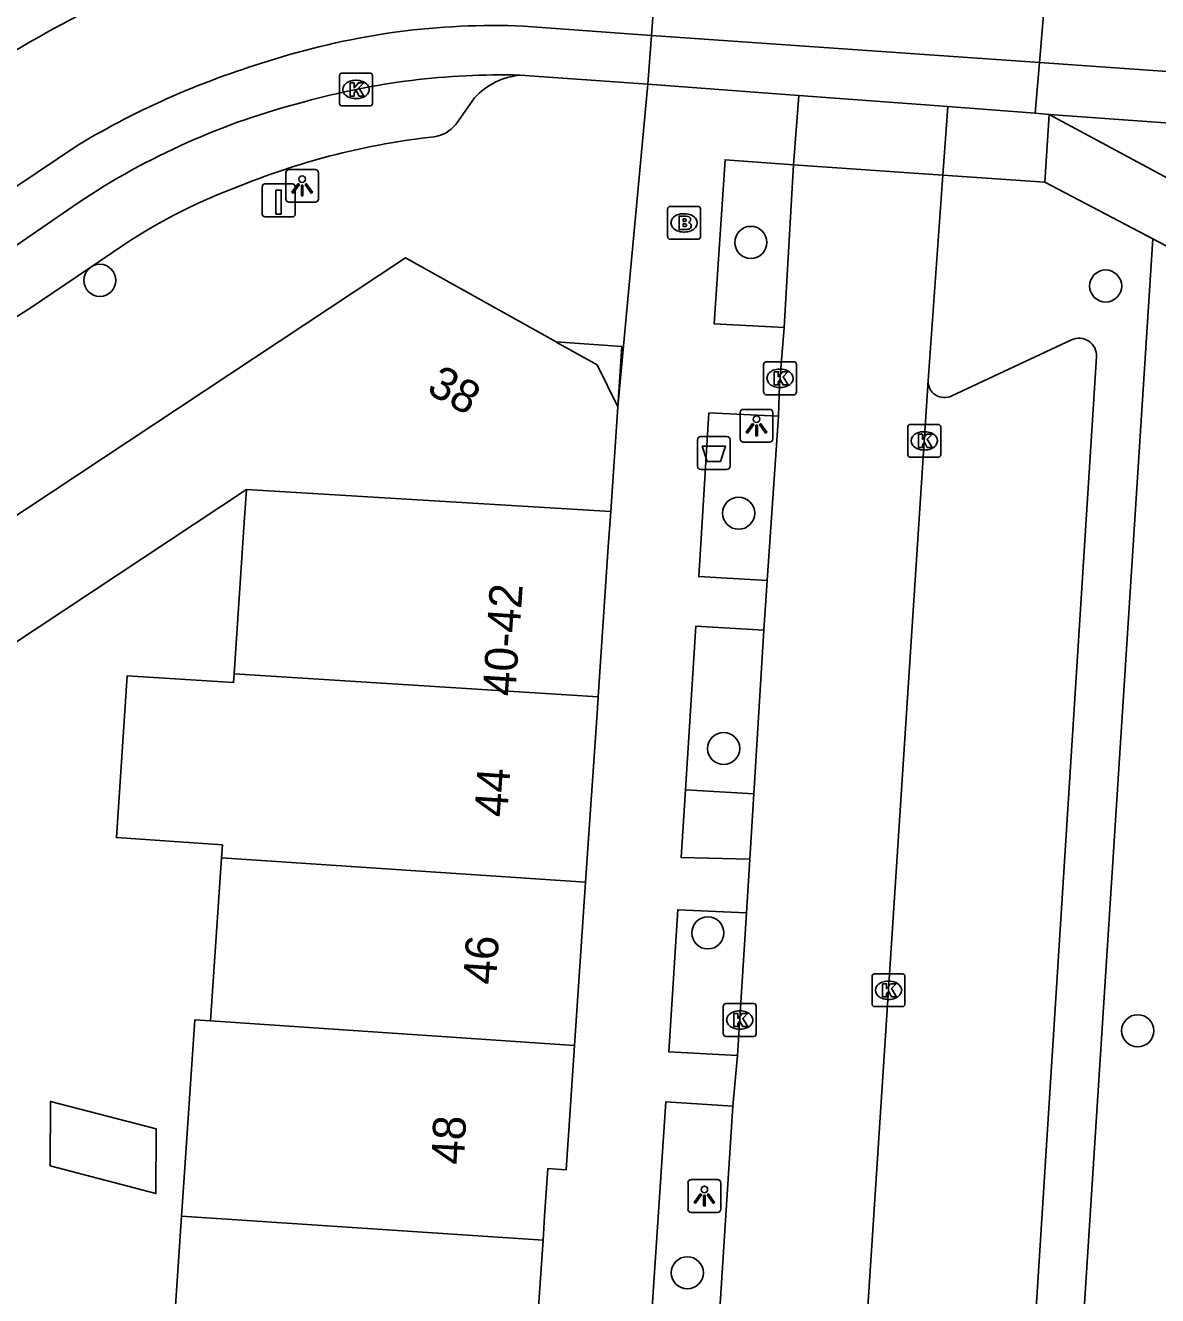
# Model space of a CAD drawing. Extents: x 159961 to 160856, y 382704 to 383353.
# Drawn here: x 160554.44 to 160588.94, y 382899.59 to 382938.31 of the extents above; entities that cross this region are included whole.
import ezdxf

# ---------------------------------------------------------------- set-up
doc = ezdxf.new("R2010")
doc.units = 0
for name, color, linetype in [('IMGEO_Afvalbak', 7, 'Continuous'), ('IMGEO_Boom', 7, 'Continuous'), ('IMGEO_Brandkraan', 7, 'Continuous'), ('IMGEO_Groenvoorziening', 7, 'Continuous'), ('IMGEO_Kolk', 7, 'Continuous'), ('IMGEO_Laadpaal', 7, 'Continuous'), ('IMGEO_Lichtpunt', 7, 'Continuous'), ('IMGEO_Pand', 7, 'Continuous'), ('IMGEO_Pand_nummerreeks', 7, 'Continuous'), ('IMGEO_Pand_overbouw', 7, 'Continuous'), ('IMGEO_Parkeervlak_open', 7, 'Continuous'), ('IMGEO_Rijbaan_lokaal_gesloten', 7, 'Continuous'), ('IMGEO_Rijbaan_lokaal_open', 7, 'Continuous'), ('IMGEO_Voetpad_halfverhard', 7, 'Continuous'), ('IMGEO_Voetpad_open', 7, 'Continuous')]:
    doc.layers.add(name, color=color, linetype=linetype)

msp = doc.modelspace()

# ---------------------------------------------------------------- linework, layer by layer
at = {"layer": 'IMGEO_Afvalbak'}
for p, q in [((160575.023, 382925.776), (160575.813, 382925.776)), ((160575.813, 382925.776), (160575.023, 382925.776)), ((160574.923, 382924.876), (160574.923, 382925.676)), ((160574.923, 382925.676), (160574.923, 382924.876)), ((160575.913, 382925.676), (160575.913, 382924.876)), ((160575.913, 382924.876), (160575.913, 382925.676)), ((160575.813, 382924.776), (160575.023, 382924.776)), ((160575.023, 382924.776), (160575.813, 382924.776))]:
    msp.add_line(p, q, dxfattribs=at)
msp.add_lwpolyline([(160575.066, 382925.49), (160575.77, 382925.49), (160575.621, 382925.02), (160575.215, 382925.02), (160575.066, 382925.49)], dxfattribs=at)
for centre, start, end in [((160575.023, 382925.676), 90, 180), ((160575.023, 382925.676), 90, 180), ((160575.813, 382925.676), 0, 90), ((160575.813, 382925.676), 360, 90), ((160575.023, 382924.876), 180, 270), ((160575.023, 382924.876), 180, 270), ((160575.813, 382924.876), 270, 0), ((160575.813, 382924.876), 270, 0)]:
    msp.add_arc(centre, 0.1, start, end, dxfattribs=at)
at = {"layer": 'IMGEO_Boom'}
for centre in [(160576.546, 382931.699), (160556.709, 382930.541), (160587.357, 382930.369), (160576.174, 382923.442), (160575.717, 382916.268), (160575.234, 382910.647), (160588.334, 382907.665), (160574.61, 382900.287)]:
    msp.add_circle(centre, 0.489, dxfattribs=at)
at = {"layer": 'IMGEO_Brandkraan'}
for p, q in [((160574.011, 382931.868), (160574.011, 382932.72)), ((160574.086, 382932.794), (160574.938, 382932.794)), ((160575.012, 382932.72), (160575.012, 382931.868)), ((160574.499, 382932.574), (160574.524, 382932.574)), ((160574.522, 382932.014), (160574.497, 382932.014)), ((160574.938, 382931.794), (160574.086, 382931.794))]:
    msp.add_line(p, q, dxfattribs=at)
for points in [[(160574.011, 382931.868), (160574.011, 382932.72)], [(160574.086, 382932.794), (160574.938, 382932.794)], [(160575.012, 382932.72), (160575.012, 382931.868)], [(160574.359, 382932.494), (160574.359, 382932.094), (160574.572, 382932.094)], [(160574.59, 382932.494), (160574.359, 382932.494)], [(160574.538, 382932.413), (160574.484, 382932.413), (160574.484, 382932.337)], [(160574.484, 382932.337), (160574.537, 382932.337)], [(160574.546, 382932.261), (160574.484, 382932.261), (160574.484, 382932.18)], [(160574.484, 382932.18), (160574.546, 382932.18)], [(160574.938, 382931.794), (160574.086, 382931.794)]]:
    msp.add_lwpolyline(points, dxfattribs=at)
for centre, radius, start, end in [((160574.088, 382932.718), 0.0765, 91.552, 178.448), ((160574.088, 382932.718), 0.0765, 91.552, 178.448), ((160574.936, 382932.718), 0.0765, 1.552, 88.448), ((160574.936, 382932.718), 0.0765, 1.552, 88.448), ((160574.539, 382932.375), 0.0379, 267.8285, 90.9355), ((160574.594, 382932.349), 0.145, 59.4692, 91.5367), ((160574.619, 382932.396), 0.0922, 285.5137, 58.1501), ((160574.624, 382932.204), 0.105, 301.3115, 78.989), ((160574.547, 382932.22), 0.0404, 269.8759, 90.5077), ((160574.578, 382932.345), 0.251, 268.6676, 293.5347), ((160574.088, 382931.87), 0.0765, 181.552, 268.448), ((160574.088, 382931.87), 0.0765, 181.552, 268.448), ((160574.936, 382931.87), 0.0765, 271.552, 358.448), ((160574.936, 382931.87), 0.0765, 271.552, 358.448)]:
    msp.add_arc(centre, radius, start, end, dxfattribs=at)
for centre, major_axis, ratio, start_param, end_param in [((160574.498, 382932.294), (-0.387, 0.002), 0.722429, 4.712389, 7.853982), ((160574.523, 382932.294), (-0.39, 0.002), 0.717154, 1.570796, 4.712389)]:
    msp.add_ellipse(centre, major_axis=major_axis, ratio=ratio, start_param=start_param, end_param=end_param, dxfattribs=at)
at = {"layer": 'IMGEO_Groenvoorziening'}
for points in [[(160585.634, 382882.567), (160588.794, 382931.802)], [(160576.637, 382914.885), (160574.552, 382915.005)]]:
    msp.add_lwpolyline(points, dxfattribs=at)
at = {"layer": 'IMGEO_Kolk'}
for p, q in [((160564.013, 382935.934), (160564.013, 382936.786)), ((160564.088, 382936.86), (160564.94, 382936.86)), ((160564.501, 382936.64), (160564.526, 382936.64)), ((160565.014, 382936.786), (160565.014, 382935.934)), ((160564.94, 382935.86), (160564.088, 382935.86)), ((160564.524, 382936.08), (160564.499, 382936.08)), ((160577.011, 382928.055), (160577.863, 382928.055)), ((160576.936, 382927.129), (160576.936, 382927.981)), ((160577.424, 382927.835), (160577.449, 382927.835)), ((160577.937, 382927.981), (160577.937, 382927.129)), ((160577.447, 382927.275), (160577.422, 382927.275)), ((160577.863, 382927.055), (160577.011, 382927.055)), ((160581.404, 382926.148), (160582.256, 382926.148)), ((160581.329, 382925.222), (160581.329, 382926.074)), ((160581.817, 382925.928), (160581.842, 382925.928)), ((160582.33, 382926.074), (160582.33, 382925.222)), ((160581.84, 382925.368), (160581.815, 382925.368)), ((160582.256, 382925.148), (160581.404, 382925.148)), ((160580.24, 382908.474), (160580.24, 382909.326)), ((160580.315, 382909.4), (160581.167, 382909.4)), ((160580.728, 382909.18), (160580.753, 382909.18)), ((160581.241, 382909.326), (160581.241, 382908.474)), ((160575.707, 382907.566), (160575.707, 382908.418)), ((160575.782, 382908.492), (160576.634, 382908.492)), ((160576.708, 382908.418), (160576.708, 382907.566)), ((160581.167, 382908.4), (160580.315, 382908.4)), ((160580.751, 382908.62), (160580.726, 382908.62)), ((160576.195, 382908.272), (160576.22, 382908.272)), ((160576.218, 382907.712), (160576.193, 382907.712)), ((160576.634, 382907.492), (160575.782, 382907.492))]:
    msp.add_line(p, q, dxfattribs=at)
for points in [[(160564.013, 382935.934), (160564.013, 382936.786)], [(160564.088, 382936.86), (160564.94, 382936.86)], [(160565.014, 382936.786), (160565.014, 382935.934)], [(160564.334, 382936.56), (160564.457, 382936.56), (160564.457, 382936.409), (160564.587, 382936.56), (160564.751, 382936.56), (160564.605, 382936.409), (160564.758, 382936.16), (160564.606, 382936.16), (160564.521, 382936.324), (160564.457, 382936.257), (160564.457, 382936.16), (160564.334, 382936.16), (160564.334, 382936.56)], [(160564.94, 382935.86), (160564.088, 382935.86)], [(160577.011, 382928.055), (160577.863, 382928.055)], [(160576.936, 382927.129), (160576.936, 382927.981)], [(160577.257, 382927.755), (160577.38, 382927.755), (160577.38, 382927.604), (160577.51, 382927.755), (160577.674, 382927.755), (160577.528, 382927.604), (160577.681, 382927.355), (160577.529, 382927.355), (160577.444, 382927.519), (160577.38, 382927.452), (160577.38, 382927.355), (160577.257, 382927.355), (160577.257, 382927.755)], [(160577.937, 382927.981), (160577.937, 382927.129)], [(160577.863, 382927.055), (160577.011, 382927.055)], [(160581.404, 382926.148), (160582.256, 382926.148)], [(160581.329, 382925.222), (160581.329, 382926.074)], [(160581.65, 382925.848), (160581.773, 382925.848), (160581.773, 382925.697), (160581.903, 382925.848), (160582.067, 382925.848), (160581.921, 382925.697), (160582.074, 382925.448), (160581.922, 382925.448), (160581.837, 382925.612), (160581.773, 382925.545), (160581.773, 382925.448), (160581.65, 382925.448), (160581.65, 382925.848)], [(160582.33, 382926.074), (160582.33, 382925.222)], [(160582.256, 382925.148), (160581.404, 382925.148)], [(160580.24, 382908.474), (160580.24, 382909.326)], [(160580.315, 382909.4), (160581.167, 382909.4)], [(160580.561, 382909.1), (160580.684, 382909.1), (160580.684, 382908.949), (160580.814, 382909.1), (160580.978, 382909.1), (160580.832, 382908.949), (160580.985, 382908.7), (160580.833, 382908.7), (160580.748, 382908.864), (160580.684, 382908.797), (160580.684, 382908.7), (160580.561, 382908.7), (160580.561, 382909.1)], [(160581.241, 382909.326), (160581.241, 382908.474)], [(160575.707, 382907.566), (160575.707, 382908.418)], [(160575.782, 382908.492), (160576.634, 382908.492)], [(160576.708, 382908.418), (160576.708, 382907.566)], [(160581.167, 382908.4), (160580.315, 382908.4)], [(160576.028, 382908.192), (160576.151, 382908.192), (160576.151, 382908.041), (160576.281, 382908.192), (160576.445, 382908.192), (160576.299, 382908.041), (160576.452, 382907.792), (160576.3, 382907.792), (160576.215, 382907.956), (160576.151, 382907.889), (160576.151, 382907.792), (160576.028, 382907.792), (160576.028, 382908.192)], [(160576.634, 382907.492), (160575.782, 382907.492)]]:
    msp.add_lwpolyline(points, dxfattribs=at)
for centre, start, end in [((160564.09, 382936.784), 91.552, 178.448), ((160564.09, 382936.784), 91.552, 178.448), ((160564.938, 382936.784), 1.552, 88.448), ((160564.938, 382936.784), 1.552, 88.448), ((160564.09, 382935.936), 181.552, 268.448), ((160564.09, 382935.936), 181.552, 268.448), ((160564.938, 382935.936), 271.552, 358.448), ((160564.938, 382935.936), 271.552, 358.448), ((160577.013, 382927.979), 91.552, 178.448), ((160577.013, 382927.979), 91.552, 178.448), ((160577.861, 382927.979), 1.552, 88.448), ((160577.861, 382927.979), 1.552, 88.448), ((160577.013, 382927.131), 181.552, 268.448), ((160577.013, 382927.131), 181.552, 268.448), ((160577.861, 382927.131), 271.552, 358.448), ((160577.861, 382927.131), 271.552, 358.448), ((160581.406, 382926.072), 91.552, 178.448), ((160581.406, 382926.072), 91.552, 178.448), ((160582.254, 382926.072), 1.552, 88.448), ((160582.254, 382926.072), 1.552, 88.448), ((160581.406, 382925.224), 181.552, 268.448), ((160581.406, 382925.224), 181.552, 268.448), ((160582.254, 382925.224), 271.552, 358.448), ((160582.254, 382925.224), 271.552, 358.448), ((160580.317, 382909.324), 91.552, 178.448), ((160580.317, 382909.324), 91.552, 178.448), ((160581.165, 382909.324), 1.552, 88.448), ((160581.165, 382909.324), 1.552, 88.448), ((160575.784, 382908.416), 91.552, 178.448), ((160575.784, 382908.416), 91.552, 178.448), ((160576.632, 382908.416), 1.552, 88.448), ((160576.632, 382908.416), 1.552, 88.448), ((160580.317, 382908.476), 181.552, 268.448), ((160580.317, 382908.476), 181.552, 268.448), ((160581.165, 382908.476), 271.552, 358.448), ((160581.165, 382908.476), 271.552, 358.448), ((160575.784, 382907.568), 181.552, 268.448), ((160575.784, 382907.568), 181.552, 268.448), ((160576.632, 382907.568), 271.552, 358.448), ((160576.632, 382907.568), 271.552, 358.448)]:
    msp.add_arc(centre, 0.0765, start, end, dxfattribs=at)
for centre, major_axis, ratio, start_param, end_param in [((160564.5, 382936.36), (-0.387, 0.002), 0.722429, 4.712389, 7.853982), ((160564.525, 382936.36), (-0.39, 0.002), 0.717154, 1.570796, 4.712389), ((160577.423, 382927.555), (-0.387, 0.002), 0.722429, 4.712389, 7.853982), ((160577.448, 382927.555), (-0.39, 0.002), 0.717154, 1.570796, 4.712389), ((160581.816, 382925.648), (-0.387, 0.002), 0.722429, 4.712389, 7.853982), ((160581.841, 382925.648), (-0.39, 0.002), 0.717154, 1.570796, 4.712389), ((160580.727, 382908.9), (-0.387, 0.002), 0.722429, 4.712389, 7.853982), ((160580.752, 382908.9), (-0.39, 0.002), 0.717154, 1.570796, 4.712389), ((160576.194, 382907.992), (-0.387, 0.002), 0.722429, 4.712389, 7.853982), ((160576.219, 382907.992), (-0.39, 0.002), 0.717154, 1.570796, 4.712389)]:
    msp.add_ellipse(centre, major_axis=major_axis, ratio=ratio, start_param=start_param, end_param=end_param, dxfattribs=at)
at = {"layer": 'IMGEO_Laadpaal'}
for p, q in [((160562.576, 382933.48), (160561.735, 382933.48)), ((160562.576, 382933.48), (160561.735, 382933.48)), ((160561.66, 382933.396), (160561.66, 382932.555)), ((160561.66, 382933.396), (160561.66, 382932.555)), ((160562.66, 382932.564), (160562.66, 382933.405)), ((160562.66, 382932.564), (160562.66, 382933.405)), ((160561.744, 382932.48), (160562.585, 382932.48)), ((160561.744, 382932.48), (160562.585, 382932.48))]:
    msp.add_line(p, q, dxfattribs=at)
msp.add_lwpolyline([(160562.075, 382933.293), (160562.235, 382933.293), (160562.235, 382932.56), (160562.075, 382932.56), (160562.075, 382933.293)], dxfattribs=at)
for centre, start, end in [((160561.738, 382933.402), 92.4484, 184.2845), ((160561.738, 382933.402), 92.4484, 184.2845), ((160562.582, 382933.402), 2.4484, 94.2845), ((160562.582, 382933.402), 2.4484, 94.2845), ((160561.738, 382932.558), 182.4484, 274.2845), ((160561.738, 382932.558), 182.4484, 274.2845), ((160562.582, 382932.558), 272.4484, 4.2845), ((160562.582, 382932.558), 272.4484, 4.2845)]:
    msp.add_arc(centre, 0.0779, start, end, dxfattribs=at)
at = {"layer": 'IMGEO_Lichtpunt'}
for p, q in [((160563.278, 382933.922), (160562.47, 382933.922)), ((160563.278, 382933.922), (160562.47, 382933.922)), ((160562.376, 382933.827), (160562.376, 382933.02)), ((160562.376, 382933.827), (160562.376, 382933.02)), ((160563.372, 382933.02), (160563.372, 382933.827)), ((160563.372, 382933.02), (160563.372, 382933.827)), ((160562.47, 382932.926), (160563.278, 382932.926)), ((160562.47, 382932.926), (160563.278, 382932.926)), ((160576.221, 382926.512), (160576.221, 382925.705)), ((160576.221, 382926.512), (160576.221, 382925.705)), ((160577.123, 382926.607), (160576.315, 382926.607)), ((160577.123, 382926.607), (160576.315, 382926.607)), ((160577.217, 382925.705), (160577.217, 382926.512)), ((160577.217, 382925.705), (160577.217, 382926.512)), ((160576.315, 382925.611), (160577.123, 382925.611)), ((160576.315, 382925.611), (160577.123, 382925.611)), ((160574.631, 382903.03), (160574.631, 382902.223)), ((160574.631, 382903.03), (160574.631, 382902.223)), ((160575.533, 382903.125), (160574.725, 382903.125)), ((160575.533, 382903.125), (160574.725, 382903.125)), ((160575.627, 382902.223), (160575.627, 382903.03)), ((160575.627, 382902.223), (160575.627, 382903.03)), ((160574.725, 382902.129), (160575.533, 382902.129)), ((160574.725, 382902.129), (160575.533, 382902.129))]:
    msp.add_line(p, q, dxfattribs=at)
for points in [[(160562.75, 382933.491), (160562.789, 382933.463), (160562.601, 382933.201), (160562.563, 382933.228), (160562.75, 382933.491)], [(160562.962, 382933.463), (160563, 382933.49), (160563.187, 382933.228), (160563.148, 382933.2), (160562.962, 382933.463)], [(160562.852, 382933.443), (160562.899, 382933.443), (160562.899, 382933.121), (160562.852, 382933.121), (160562.852, 382933.443)], [(160576.595, 382926.176), (160576.634, 382926.148), (160576.446, 382925.886), (160576.408, 382925.913), (160576.595, 382926.176)], [(160576.697, 382926.128), (160576.744, 382926.128), (160576.744, 382925.806), (160576.697, 382925.806), (160576.697, 382926.128)], [(160576.807, 382926.148), (160576.845, 382926.175), (160577.032, 382925.913), (160576.993, 382925.885), (160576.807, 382926.148)], [(160575.005, 382902.694), (160575.044, 382902.666), (160574.856, 382902.404), (160574.818, 382902.431), (160575.005, 382902.694)], [(160575.107, 382902.646), (160575.154, 382902.646), (160575.154, 382902.324), (160575.107, 382902.324), (160575.107, 382902.646)], [(160575.217, 382902.666), (160575.255, 382902.693), (160575.442, 382902.431), (160575.403, 382902.403), (160575.217, 382902.666)]]:
    msp.add_lwpolyline(points, dxfattribs=at)
for centre in [(160562.875, 382933.625), (160576.72, 382926.31), (160575.13, 382902.828)]:
    msp.add_circle(centre, 0.0994, dxfattribs=at)
for centre, start, end in [((160562.47, 382933.827), 90, 180), ((160562.47, 382933.827), 90, 180), ((160563.278, 382933.827), 0, 90), ((160563.278, 382933.827), 0, 90), ((160562.47, 382933.02), 180, 270), ((160562.47, 382933.02), 180, 270), ((160563.278, 382933.02), 270, 0), ((160563.278, 382933.02), 270, 360), ((160576.315, 382926.512), 90, 180), ((160576.315, 382926.512), 90, 180), ((160577.123, 382926.512), 0, 90), ((160577.123, 382926.512), 0, 90), ((160576.315, 382925.705), 180, 270), ((160576.315, 382925.705), 180, 270), ((160577.123, 382925.705), 270, 0), ((160577.123, 382925.705), 270, 360), ((160574.725, 382903.03), 90, 180), ((160574.725, 382903.03), 90, 180), ((160575.533, 382903.03), 0, 90), ((160575.533, 382903.03), 0, 90), ((160574.725, 382902.223), 180, 270), ((160574.725, 382902.223), 180, 270), ((160575.533, 382902.223), 270, 0), ((160575.533, 382902.223), 270, 360)]:
    msp.add_arc(centre, 0.0946, start, end, dxfattribs=at)
at = {"layer": 'IMGEO_Pand'}
for points in [[(160548.356, 382919.53), (160566.024, 382931.226), (160570.61, 382928.664), (160570.636, 382928.65), (160571.865, 382927.963), (160572.49, 382926.689)], [(160572.49, 382926.689), (160572.275, 382923.497)], [(160548.356, 382919.53), (160550.128, 382916.853), (160561.177, 382924.168)], [(160560.797, 382918.55), (160561.109, 382923.159), (160561.177, 382924.168)], [(160561.177, 382924.168), (160572.275, 382923.497)], [(160572.275, 382923.497), (160572.202, 382922.421), (160571.893, 382917.847)], [(160560.797, 382918.55), (160560.779, 382918.281), (160557.545, 382918.486), (160557.212, 382913.553), (160560.445, 382913.334), (160560.418, 382912.933)], [(160571.893, 382917.847), (160560.797, 382918.55)], [(160571.893, 382917.847), (160571.859, 382917.347), (160571.511, 382912.196)], [(160560.082, 382907.962), (160560.418, 382912.933)], [(160560.418, 382912.933), (160571.511, 382912.196)], [(160571.511, 382912.196), (160571.174, 382907.212)], [(160560.082, 382907.962), (160559.604, 382907.994), (160559.249, 382902.745), (160559.2, 382902.014)], [(160571.174, 382907.212), (160560.082, 382907.962)], [(160571.174, 382907.212), (160570.918, 382903.429), (160570.361, 382903.466), (160570.263, 382902.012), (160570.214, 382901.282)], [(160555.191, 382903.543), (160555.201, 382905.51), (160558.429, 382904.671), (160558.419, 382902.703), (160555.191, 382903.543)], [(160558.833, 382896.589), (160558.964, 382898.52), (160559.2, 382902.014)], [(160559.2, 382902.014), (160570.214, 382901.282)], [(160570.214, 382901.282), (160569.977, 382897.787), (160569.847, 382895.857)]]:
    msp.add_lwpolyline(points, dxfattribs=at)
at = {"layer": 'IMGEO_Pand_overbouw'}
msp.add_lwpolyline([(160572.614, 382928.529), (160570.61, 382928.664), (160570.636, 382928.65), (160571.865, 382927.963), (160572.49, 382926.689)], close=True, dxfattribs=at)
at = {"layer": 'IMGEO_Parkeervlak_open'}
for points in [[(160586.314, 382928.724), (160582.667, 382927.021)], [(160584.487, 382887.345), (160587.079, 382928.212)]]:
    msp.add_lwpolyline(points, dxfattribs=at)
for centre, radius, start, end in [((160586.545, 382928.241), 0.535, 356.8879, 115.5248), ((160582.443, 382927.463), 0.496, 177.3666, 296.8494)]:
    msp.add_arc(centre, radius, start, end, dxfattribs=at)
at = {"layer": 'IMGEO_Rijbaan_lokaal_gesloten'}
for points in [[(160573.519, 382938.007), (160569.62, 382938.295)], [(160585.337, 382937.184), (160616.323, 382934.993), (160616.183, 382933.536)], [(160573.407, 382936.518), (160569.518, 382936.799)], [(160585.637, 382935.602), (160585.207, 382935.643)], [(160585.637, 382935.602), (160591.872, 382935.149), (160602.388, 382934.447), (160606.128, 382934.233), (160616.183, 382933.536)], [(160556.038, 382934.664), (160528.518, 382916.17)], [(160556.052, 382932.908), (160553.525, 382931.179), (160532.63, 382917.129)]]:
    msp.add_lwpolyline(points, dxfattribs=at)
for centre, radius, start, end in [((160568.72, 382913.478), 28.141, 105.7061, 124.2743), ((160568.747, 382915.902), 22.41, 87.7675, 107.4386), ((160569.305, 382912.462), 25.864, 106.3346, 120.861), ((160568.971, 382914.276), 22.53, 88.608, 105.5024), ((160568.495, 382914.293), 22.391, 104.3406, 123.76)]:
    msp.add_arc(centre, radius, start, end, dxfattribs=at)
at = {"layer": 'IMGEO_Rijbaan_lokaal_open'}
for points in [[(160573.775, 382941.428), (160573.519, 382938.007)], [(160585.624, 382940.588), (160585.337, 382937.184)], [(160573.519, 382938.007), (160573.407, 382936.518)], [(160585.337, 382937.184), (160573.519, 382938.007)], [(160585.207, 382935.643), (160585.337, 382937.184)], [(160578.01, 382936.176), (160573.407, 382936.518)], [(160577.849, 382934.058), (160578.01, 382936.176)], [(160578.01, 382936.176), (160582.548, 382935.84)], [(160582.398, 382933.745), (160582.548, 382935.84)], [(160582.548, 382935.84), (160585.207, 382935.643)], [(160577.849, 382934.058), (160577.566, 382929.1)], [(160582.398, 382933.745), (160577.849, 382934.058)], [(160581.948, 382927.486), (160582.398, 382933.745)], [(160577.566, 382929.1), (160577.42, 382927.341), (160577.386, 382926.4)], [(160579.079, 382883.337), (160581.948, 382927.486)], [(160577.386, 382926.4), (160577.048, 382921.391)], [(160577.048, 382921.391), (160576.946, 382919.875)], [(160576.946, 382919.875), (160576.637, 382914.885)], [(160576.637, 382914.885), (160576.513, 382912.893)], [(160576.513, 382912.893), (160576.412, 382911.263)], [(160576.412, 382911.263), (160576.142, 382906.91)], [(160576.142, 382906.91), (160575.998, 382905.366)], [(160575.998, 382905.366), (160575.423, 382896.333)]]:
    msp.add_lwpolyline(points, dxfattribs=at)
at = {"layer": 'IMGEO_Voetpad_halfverhard'}
for points in [[(160616.315, 382929.418), (160594.851, 382931.047), (160593.305, 382931.469), (160585.637, 382935.602)], [(160585.502, 382933.53), (160588.794, 382931.802)], [(160588.794, 382931.802), (160591.356, 382930.458)]]:
    msp.add_lwpolyline(points, dxfattribs=at)
at = {"layer": 'IMGEO_Voetpad_open'}
for points in [[(160573.407, 382936.518), (160572.49, 382926.689)], [(160568.126, 382936.106), (160567.555, 382935.291)], [(160585.637, 382935.602), (160585.502, 382933.53)], [(160577.566, 382929.1), (160575.429, 382929.215), (160575.761, 382934.217), (160577.849, 382934.058)], [(160585.502, 382933.53), (160582.398, 382933.745)], [(160557.444, 382931.626), (160554.583, 382929.698), (160553.929, 382929.281), (160552.781, 382928.509)], [(160577.048, 382921.391), (160574.956, 382921.512), (160575.266, 382926.502), (160577.386, 382926.4)], [(160574.552, 382915.005), (160574.869, 382919.995), (160576.946, 382919.875)], [(160576.513, 382912.893), (160574.421, 382912.946), (160574.552, 382915.005)], [(160576.142, 382906.91), (160574.046, 382907.023), (160574.321, 382911.355), (160576.412, 382911.263)], [(160573.359, 382896.487), (160573.959, 382905.499), (160575.998, 382905.366)]]:
    msp.add_lwpolyline(points, dxfattribs=at)
for centre, radius, start, end in [((160569.717, 382934.654), 2.154, 95.3076, 137.6248), ((160566.748, 382935.952), 1.043, 278.1181, 320.6963), ((160569.361, 382912.777), 22.279, 96.3553, 111.9425), ((160566.904, 382917.374), 17.106, 110.0633, 123.5761)]:
    msp.add_arc(centre, radius, start, end, dxfattribs=at)

# ---------------------------------------------------------------- texts
at = {"layer": 'IMGEO_Pand_nummerreeks'}
for s, rotation, p in [('38', 330.8078, (160566.629, 382927.131)), ('40-42', 86.1339, (160569.367, 382917.846)), ('44', 86.1327, (160569.118, 382914.158)), ('46', 86.1333, (160568.773, 382909.052)), ('48', 87.2201, (160567.802, 382903.568))]:
    msp.add_text(s, height=1, rotation=rotation, dxfattribs=at).set_placement(p)

doc.saveas('drawing.dxf')
